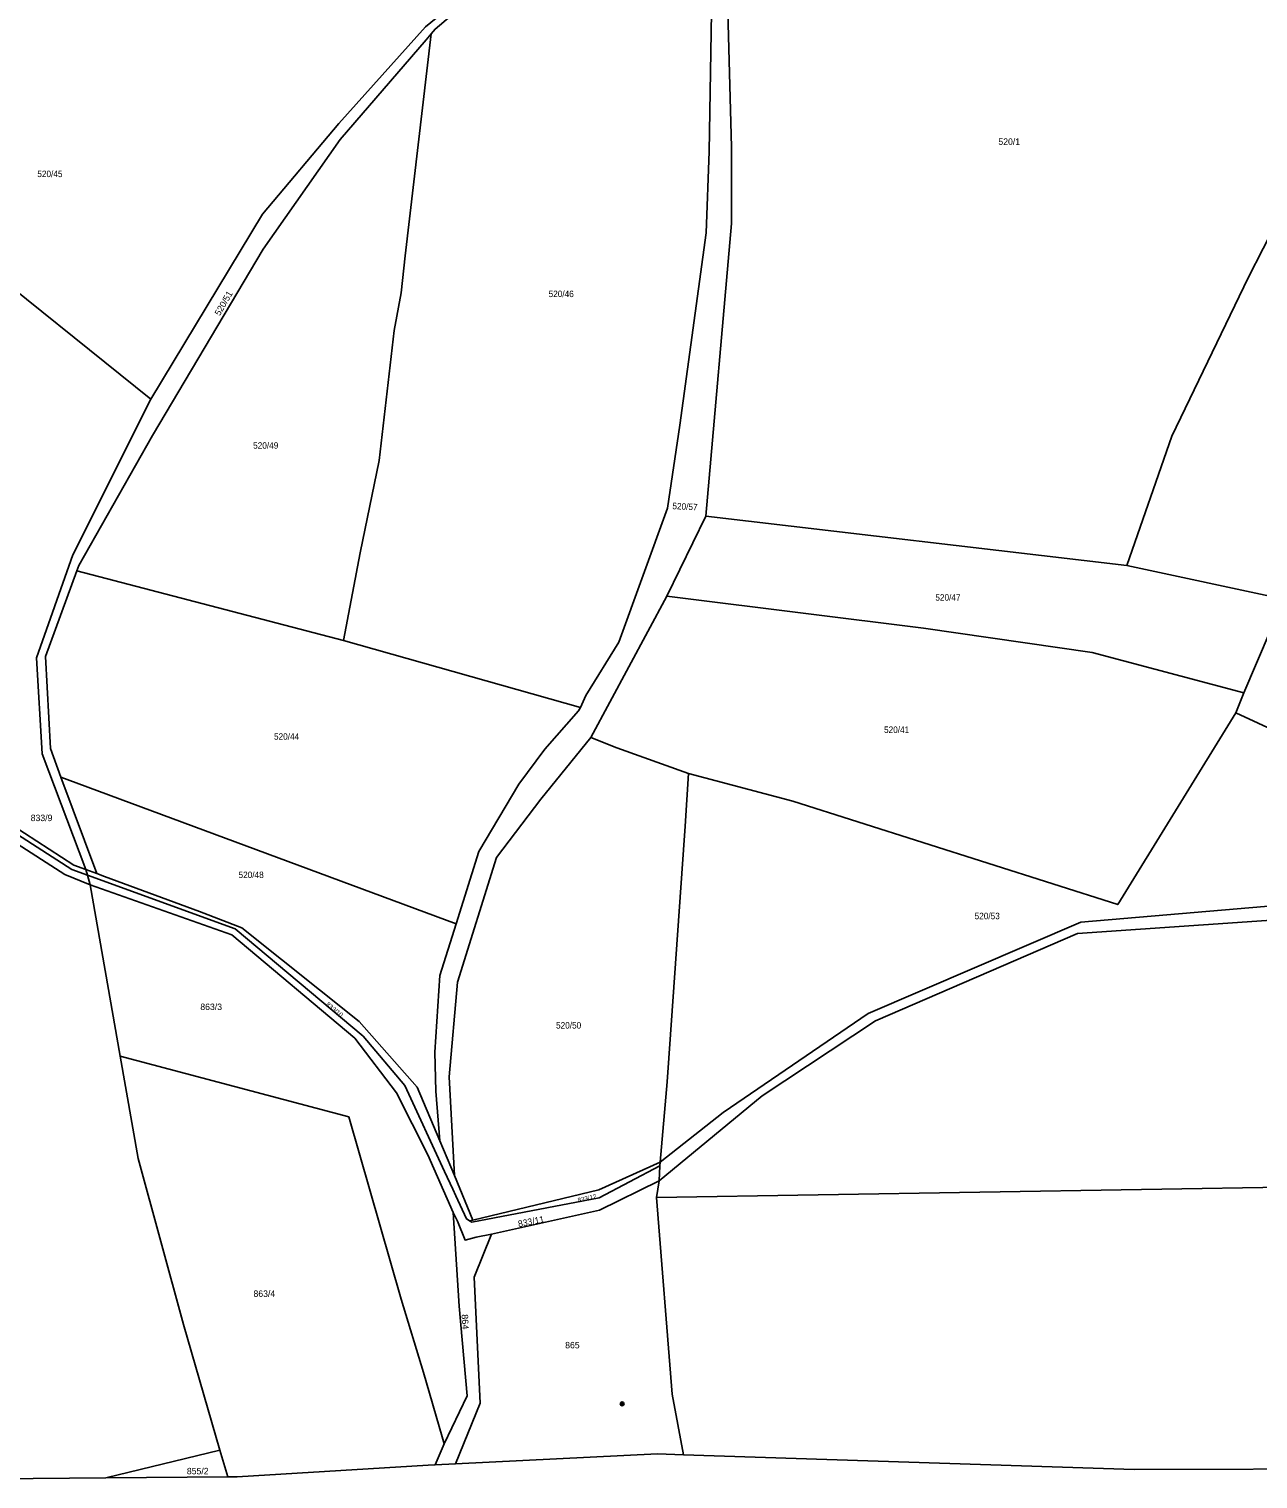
# Model space of a CAD drawing. Extents: x -687135 to -684370, y -1007309 to -1005782.
# Drawn here: x -685632.3 to -685309.9, y -1007304.7 to -1006924.3 of the extents above; entities that cross this region are included whole.
import ezdxf

# ---------------------------------------------------------------- set-up
doc = ezdxf.new("R2010")
doc.units = 0
doc.header["$LTSCALE"] = 0.68
doc.layers.add('1', color=7, linetype='Continuous', lineweight=25)
doc.layers.add('6', color=7, linetype='Continuous', lineweight=25)
doc.layers.add('2', color=7, linetype='Continuous')

msp = doc.modelspace()

# ---------------------------------------------------------------- linework, layer by layer
at = {"layer": '1'}
for p, q in [((-685454.75, -1007052.16), (-685465.02, -1007073.11)), ((-685315.69, -1007103.71), (-685313.64, -1007098.44)), ((-685623.89, -1007120.58), (-685614.48, -1007145.9)), ((-685617.35, -1007144.84), (-685614.48, -1007145.9)), ((-685616.95, -1007146.31), (-685617.35, -1007144.84)), ((-685524.56, -1007216), (-685520.71, -1007225.15)), ((-685467.65, -1007230.89), (-685467.01, -1007226.55)), ((-685516.75, -1007236.97), (-685515.85, -1007236.85)), ((-685525.74, -1007301.04), (-685520.37, -1007300.72)), ((-685612.11, -1007304.44), (-685648.07, -1007304.74))]:
    msp.add_line(p, q, dxfattribs=at)
for points in [[(-685344.34, -1007065.04), (-685332.49, -1007031.1), (-685312.53, -1006989.57), (-685304.62, -1006974.15), (-685262.73, -1006903.67), (-685259.07, -1006896.13), (-685253.74, -1006885.14), (-685252.41, -1006882.51), (-685229.3, -1006836.82), (-685196.87, -1006776.1)], [(-685472.04, -1006855.16), (-685465.95, -1006858.14), (-685451.07, -1006873.02), (-685449.67, -1006893.75), (-685448.06, -1006955.29), (-685448.01, -1006975.35), (-685454.75, -1007052.16), (-685344.34, -1007065.04)], [(-685600.31, -1007021.4), (-685571.01, -1006972.89), (-685550.99, -1006949.11), (-685528.25, -1006923.76), (-685506.88, -1006906.22), (-685488.26, -1006889.79), (-685469.63, -1006872.88), (-685468.63, -1006862.64)], [(-685464.49, -1006866.84), (-685466.45, -1006875.07), (-685491.38, -1006895.96), (-685505.02, -1006906.65), (-685525.78, -1006924.31), (-685526.83, -1006925.6)], [(-685487.65, -1007102.28), (-685486.22, -1007099.21), (-685477.56, -1007085.22), (-685464.8, -1007050), (-685461.61, -1007028.25), (-685454.62, -1006977.75), (-685453.91, -1006956.43), (-685453.17, -1006914.64), (-685452.94, -1006891.57), (-685454.7, -1006876.89), (-685464.49, -1006866.84)], [(-685526.83, -1006925.6), (-685528.14, -1006927.12), (-685550.67, -1006953.29), (-685570.84, -1006982.06), (-685599.89, -1007030.93), (-685619.23, -1007065.08), (-685619.72, -1007066.43)], [(-685526.83, -1006925.6), (-685533.65, -1006983.84), (-685534.7, -1006993.56), (-685536.54, -1007003.43), (-685540.4, -1007037.48), (-685545.39, -1007061.72), (-685549.8, -1007084.77)], [(-685617.35, -1007144.84), (-685628.86, -1007114.49), (-685630.33, -1007089.27), (-685620.78, -1007062.3), (-685600.31, -1007021.4), (-685697.79, -1006943.02)], [(-685619.72, -1007066.43), (-685627.99, -1007088.96), (-685626.67, -1007113.08), (-685623.89, -1007120.58)], [(-685520.27, -1007159.09), (-685514.28, -1007140.13), (-685503.84, -1007122.39), (-685496.95, -1007113.29), (-685488.15, -1007103.15), (-685487.65, -1007102.28), (-685549.8, -1007084.77), (-685619.72, -1007066.43)], [(-685313.64, -1007098.44), (-685303.16, -1007073.92), (-685344.34, -1007065.04)], [(-685313.64, -1007098.44), (-685353.38, -1007087.85), (-685397.64, -1007081.53), (-685461.46, -1007073.55), (-685465.02, -1007073.11), (-685484.91, -1007110.15)], [(-685466.75, -1007221.61), (-685450.23, -1007208.57), (-685412.2, -1007182.63), (-685356.43, -1007158.68), (-685304.07, -1007154.21), (-685281.05, -1007151.78), (-685230, -1007143.45), (-685315.69, -1007103.71)], [(-685459.33, -1007119.6), (-685431.91, -1007126.89), (-685346.7, -1007154.02), (-685315.69, -1007103.71)], [(-685676.52, -1007110.47), (-685651.64, -1007127.65), (-685622.91, -1007146.17), (-685616.25, -1007148.85), (-685616.95, -1007146.31)], [(-685484.91, -1007110.15), (-685498.04, -1007126.39), (-685509.7, -1007141.66), (-685519.86, -1007174.4), (-685522.05, -1007199.22), (-685520.71, -1007225.15), (-685515.85, -1007236.85)], [(-685484.91, -1007110.15), (-685478.12, -1007112.87), (-685459.33, -1007119.6)], [(-685466.75, -1007221.61), (-685464.93, -1007200.54), (-685460.19, -1007133.41), (-685459.33, -1007119.6)], [(-685623.89, -1007120.58), (-685622.25, -1007121.19), (-685520.27, -1007159.09)], [(-685616.95, -1007146.31), (-685621.04, -1007144.83), (-685648.4, -1007127.2)], [(-685643.28, -1007129), (-685620.51, -1007143.68), (-685617.35, -1007144.84)], [(-685079.98, -1007130.44), (-685090.5, -1007131.27), (-685129.34, -1007130.78), (-685158.74, -1007134.7), (-685179.81, -1007137.96), (-685203.27, -1007142.38), (-685214.38, -1007144.66), (-685249, -1007151.04), (-685291.14, -1007157.08), (-685357.28, -1007161.65), (-685410.25, -1007184.52), (-685439.97, -1007204.17), (-685467.01, -1007226.55)], [(-685616.95, -1007146.31), (-685578.21, -1007160.36), (-685544.64, -1007188.56), (-685533.7, -1007201.48), (-685523.29, -1007224.05), (-685521.14, -1007228.71), (-685520.34, -1007230.43), (-685517.55, -1007236.48), (-685517.11, -1007236.75), (-685516.75, -1007236.97)], [(-685614.48, -1007145.9), (-685612.47, -1007146.64), (-685587.57, -1007155.81), (-685576.45, -1007160.11), (-685545.64, -1007184.72), (-685530.46, -1007201.97), (-685524.56, -1007216)], [(-685582.19, -1007297.2), (-685591.74, -1007264.2), (-685603.63, -1007220.62), (-685608.39, -1007193.83), (-685616.25, -1007148.85)], [(-685616.25, -1007148.85), (-685579.06, -1007161.99), (-685546.83, -1007189.09), (-685535.89, -1007203.45), (-685527.65, -1007219.7), (-685521.06, -1007234.78)], [(-685524.56, -1007216), (-685525.54, -1007202.94), (-685525.83, -1007192.74), (-685524.54, -1007172.63), (-685520.27, -1007159.09)], [(-685608.39, -1007193.83), (-685548.39, -1007209.72), (-685534.63, -1007257.55), (-685528.81, -1007276.84), (-685523.88, -1007293.64), (-685523.35, -1007295.47)], [(-685466.83, -1007222.6), (-685482.73, -1007230.96), (-685516.17, -1007237.32), (-685516.75, -1007236.97)], [(-685515.85, -1007236.85), (-685482.85, -1007228.83), (-685466.75, -1007221.61)], [(-685466.75, -1007221.61), (-685466.83, -1007222.6), (-685467.01, -1007226.55)], [(-685467.65, -1007230.89), (-685213.25, -1007226.72), (-685138.93, -1007223.3)], [(-685467.01, -1007226.55), (-685482.64, -1007234.19), (-685511.01, -1007240.5)], [(-685460.59, -1007298.38), (-685463.55, -1007282.48), (-685467.65, -1007230.89)], [(-685521.06, -1007234.78), (-685519.48, -1007259.42), (-685517.32, -1007282.88), (-685523.35, -1007295.47), (-685525.74, -1007301.04)], [(-685511.01, -1007240.5), (-685514.95, -1007241.29), (-685517.91, -1007242.07), (-685519.92, -1007237.05), (-685521.06, -1007234.78)], [(-685520.37, -1007300.72), (-685513.91, -1007284.86), (-685515.53, -1007251.81), (-685511.01, -1007240.5)], [(-685520.37, -1007300.72), (-685467.44, -1007298.16), (-685460.59, -1007298.38)], [(-685460.59, -1007298.38), (-685342.44, -1007302.24), (-685154.86, -1007301.68)], [(-685525.74, -1007301.04), (-685527.56, -1007301.15), (-685577.7, -1007304.16), (-685580.16, -1007304.18)]]:
    msp.add_lwpolyline(points, dxfattribs=at)
msp.add_lwpolyline([(-685582.19, -1007297.2), (-685612.11, -1007304.44), (-685580.16, -1007304.18)], close=True, dxfattribs=at)
at = {"layer": '6'}
for radius in [0.5, 0.4, 0.3, 0.2, 0.1]:
    msp.add_circle((-685476.7134, -1007285.0299), radius, dxfattribs=at)

# ---------------------------------------------------------------- texts
at = {"layer": '2'}
for s, p in [('520/1', (-685378.01, -1006954.7)), ('833/9', (-685631.83, -1007132.13)), ('863/3', (-685587.34, -1007181.7)), ('863/4', (-685573.4, -1007256.97)), ('865', (-685491.64, -1007270.47)), ('855/2', (-685590.87, -1007303.52))]:
    msp.add_text(s, height=1.7, dxfattribs=at).set_placement(p)
at = {"layer": '2', "width": 0.95}
for s, p in [('520/45', (-685630.1, -1006963.16)), ('520/46', (-685495.99, -1006994.64)), ('520/49', (-685573.49, -1007034.419)), ('520/47', (-685394.55, -1007074.289)), ('520/41', (-685408.01, -1007109)), ('520/44', (-685568.02, -1007110.789)), ('520/48', (-685577.32, -1007147.07)), ('520/53', (-685384.25, -1007157.87)), ('520/50', (-685494.04, -1007186.559))]:
    msp.add_text(s, height=1.7, dxfattribs=at).set_placement(p)
at = {"layer": '2'}
for s, height, rotation, p in [('520/51', 1.7, 60, (-685582.243, -1006999.685)), ('833/12', 1.19, 13, (-685488.216, -1007232.219)), ('833/11', 1.7, 11, (-685503.847, -1007238.674))]:
    msp.add_text(s, height=height, rotation=rotation, dxfattribs=at).set_placement(p)
for s, height, rotation, width, p in [('520/57', 1.7, 357, 0.95, (-685463.554, -1007050.268)), ('833/10', 1.19, 321, 1.05, (-685554.494, -1007180.442)), ('864', 1.7, 273, 1.05, (-685518.828, -1007261.554))]:
    msp.add_text(s, height=height, rotation=rotation, dxfattribs=dict(at, width=width)).set_placement(p)

doc.saveas('drawing.dxf')
